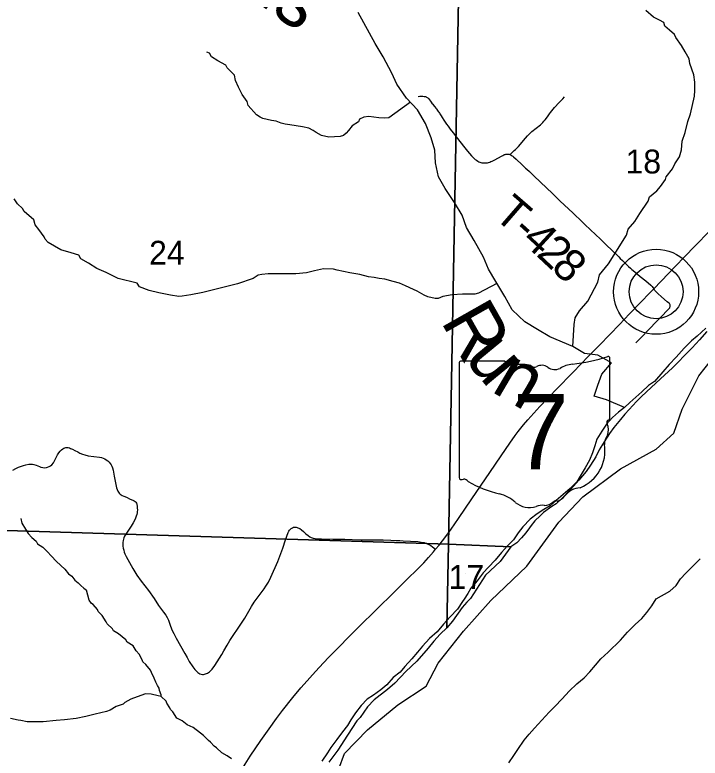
# Model space of a CAD drawing. Extents: x 6.3 to 40.3, y 9 to 31.
# Drawn here: x 9.509 to 10.708, y 23.853 to 25.154 of the extents above; entities that cross this region are included whole.
import ezdxf

# ---------------------------------------------------------------- set-up
doc = ezdxf.new("R2010")
doc.units = 0
for name, color, linetype in [('Default', 7, 'Continuous'), ('GM_X_Major_River', 7, 'Continuous'), ('GM_X_Minor_River', 7, 'Continuous'), ('GM_X_Minor_River_Text', 7, 'Continuous'), ('GM_X_Section', 7, 'Continuous'), ('GM_X_Section_Text', 7, 'Continuous'), ('GM_X_State_Location', 7, 'Continuous'), ('GM_X_State_Route', 7, 'Continuous'), ('GM_X_State_Shield', 7, 'Continuous'), ('GM_X_Township_Road', 7, 'Continuous'), ('GM_X_Township_Road_Text', 7, 'Continuous'), ('GM_X_Unincorporated', 7, 'Continuous'), ('GM_X_Unincorporated_Location', 7, 'Continuous'), ('SH_Cut_Line', 7, 'Continuous')]:
    doc.layers.add(name, color=color, linetype=linetype)

msp = doc.modelspace()

# ---------------------------------------------------------------- linework, layer by layer
at = {"layer": 'Default'}
msp.add_lwpolyline([(10.0659, 23.8074), (10.0861, 23.8612), (10.1261, 23.9024), (10.1794, 23.946), (10.2287, 23.9786), (10.2497, 24.0192), (10.2941, 24.0752), (10.3423, 24.1287), (10.4051, 24.1886), (10.4609, 24.2658), (10.5028, 24.3104), (10.5689, 24.3593), (10.6314, 24.3933), (10.6625, 24.4218), (10.6767, 24.4634), (10.7062, 24.5216), (10.7617, 24.5919)], dxfattribs=at)
at = {"layer": 'GM_X_Major_River'}
for points in [[(10.7184, 24.6053), (10.7031, 24.5914), (10.693, 24.5832), (10.6804, 24.5705), (10.6662, 24.5547), (10.6539, 24.5419), (10.6428, 24.5288), (10.6283, 24.5119), (10.6182, 24.5049), (10.6063, 24.494), (10.5854, 24.4754), (10.5757, 24.4665), (10.5656, 24.4584), (10.5551, 24.4491), (10.5447, 24.4372), (10.5362, 24.4249), (10.5273, 24.411), (10.5238, 24.3992), (10.5198, 24.387), (10.5147, 24.374), (10.507, 24.361), (10.4982, 24.3464), (10.4923, 24.3364), (10.4807, 24.3249), (10.4684, 24.314), (10.4564, 24.3036), (10.446, 24.2946), (10.4347, 24.288), (10.4231, 24.2806), (10.4108, 24.2712), (10.3981, 24.2574), (10.3899, 24.2473), (10.3818, 24.2351), (10.3714, 24.2242), (10.3606, 24.2127), (10.3495, 24.1992), (10.3379, 24.1868), (10.3286, 24.1772), (10.3179, 24.163), (10.3071, 24.1502), (10.3016, 24.1407), (10.2953, 24.1311), (10.2923, 24.1267)], [(10.6553, 24.1449), (10.6665, 24.155), (10.6742, 24.1665), (10.6835, 24.1765), (10.6951, 24.1881), (10.7085, 24.2016)], [(10.3734, 23.8446), (10.3823, 23.8576), (10.389, 23.868), (10.4004, 23.8845), (10.409, 23.8945), (10.4187, 23.9052), (10.4313, 23.9191), (10.4443, 23.9334), (10.454, 23.943), (10.4667, 23.9565), (10.479, 23.97), (10.4928, 23.9831), (10.5055, 23.9936), (10.5151, 24.0036), (10.5252, 24.0155), (10.5348, 24.0267), (10.5475, 24.0383), (10.5692, 24.0591), (10.581, 24.0733), (10.5948, 24.0865), (10.6064, 24.0969), (10.6153, 24.1077), (10.6238, 24.1192), (10.6315, 24.1314), (10.6553, 24.1449)], [(10.2923, 24.1267), (10.2838, 24.1133), (10.2711, 24.1002), (10.2592, 24.0871), (10.2481, 24.0736), (10.2346, 24.062), (10.2227, 24.0489), (10.2138, 24.0385), (10.2038, 24.0266), (10.1915, 24.0131), (10.1833, 24.0031), (10.1714, 23.9938), (10.1598, 23.9811), (10.1494, 23.9722), (10.137, 23.9629), (10.1258, 23.9559), (10.115, 23.9447), (10.1053, 23.932), (10.0972, 23.9198), (10.0913, 23.9098), (10.0824, 23.8987), (10.0724, 23.8852), (10.062, 23.8714), (10.0561, 23.8618), (10.0461, 23.8476)]]:
    msp.add_lwpolyline(points, dxfattribs=at)
at = {"layer": 'GM_X_Minor_River'}
for points in [[(10.5757, 24.4665), (10.5445, 24.4797), (10.5229, 24.4861), (10.5293, 24.5054), (10.5365, 24.5246), (10.5532, 24.5446), (10.5293, 24.5578), (10.5062, 24.5608), (10.4854, 24.5733), (10.4453, 24.5899), (10.4237, 24.6027), (10.4014, 24.6163), (10.3794, 24.6374), (10.3665, 24.6608), (10.3506, 24.6869), (10.3381, 24.7084), (10.3294, 24.7295), (10.3128, 24.759), (10.2995, 24.7812), (10.2916, 24.8031), (10.2787, 24.8254), (10.262, 24.8499), (10.2507, 24.8699), (10.245, 24.8944), (10.2442, 24.9167), (10.2374, 24.9386), (10.228, 24.9635), (10.2139, 24.9873), (10.1946, 25.008), (10.1776, 25.0322), (10.1689, 25.0518), (10.1537, 25.0801), (10.1397, 25.1035), (10.1098, 25.1575)], [(10.4854, 24.5733), (10.488, 24.6115), (10.4894, 24.6233), (10.4973, 24.6359), (10.5119, 24.6524), (10.5294, 24.6856), (10.5323, 24.6985), (10.548, 24.7177), (10.5607, 24.7383), (10.5794, 24.7681), (10.5823, 24.7784), (10.5939, 24.7918), (10.6029, 24.806), (10.6175, 24.8278), (10.6197, 24.835), (10.6325, 24.8454), (10.6392, 24.8534), (10.6478, 24.8653), (10.6489, 24.8703), (10.6602, 24.8844), (10.6642, 24.8928), (10.6721, 24.9054), (10.6754, 24.9172), (10.6771, 24.9324), (10.6823, 24.9477), (10.6866, 24.9667), (10.6914, 24.9804), (10.6987, 25.0116), (10.6993, 25.0215), (10.6988, 25.0356), (10.6971, 25.0485), (10.6905, 25.0685), (10.6892, 25.0769), (10.6823, 25.0889), (10.6757, 25.1002), (10.6657, 25.1142), (10.6637, 25.1195), (10.6545, 25.127), (10.6465, 25.1341), (10.6445, 25.1402), (10.6369, 25.1446), (10.6265, 25.1498), (10.6131, 25.1615)], [(10.2015, 25.0007), (10.1633, 24.9736), (10.1557, 24.9728), (10.1458, 24.9734), (10.1371, 24.9745), (10.1283, 24.9759), (10.12, 24.9743), (10.1124, 24.9708), (10.1106, 24.9666), (10.0996, 24.9593), (10.0929, 24.9512), (10.0891, 24.9466), (10.0842, 24.9424), (10.0786, 24.9408), (10.0588, 24.9395), (10.0455, 24.9424), (10.0363, 24.9476), (10.031, 24.9513), (10.0237, 24.9554), (10.0123, 24.9576), (9.9902, 24.9612), (9.9819, 24.9626), (9.975, 24.964), (9.9663, 24.9673), (9.9583, 24.9688), (9.943, 24.972), (9.9385, 24.9743), (9.932, 24.9788), (9.9174, 24.9949), (9.9154, 25.0021), (9.9069, 25.0142), (9.9007, 25.027), (9.8952, 25.0387), (9.8936, 25.0482), (9.8809, 25.061), (9.8786, 25.0655), (9.8645, 25.0729), (9.853, 25.0804), (9.8499, 25.0868), (9.8453, 25.0884)], [(10.3527, 24.6835), (10.3204, 24.6666), (10.3139, 24.665), (10.2927, 24.6648), (10.2741, 24.6639), (10.2581, 24.661), (10.2498, 24.6575), (10.2445, 24.6575), (10.232, 24.6604), (10.2255, 24.6633), (10.2132, 24.67), (10.2068, 24.673), (10.193, 24.6793), (10.1823, 24.6838), (10.1709, 24.6871), (10.1568, 24.6911), (10.1465, 24.6925), (10.1378, 24.6939), (10.1279, 24.6953), (10.1127, 24.699), (10.0952, 24.7022), (10.0731, 24.7069), (10.0666, 24.7087), (10.0495, 24.7093), (10.0336, 24.7057), (10.0196, 24.7021), (10.001, 24.7004), (9.9638, 24.7004), (9.9524, 24.7003), (9.9414, 24.6994), (9.935, 24.6982), (9.9263, 24.6924), (9.8987, 24.6826), (9.8381, 24.6675), (9.8173, 24.6635), (9.8021, 24.6611), (9.796, 24.6606), (9.7816, 24.6628), (9.761, 24.6671), (9.7443, 24.6715), (9.7271, 24.6774), (9.7229, 24.6841), (9.6901, 24.6922), (9.6687, 24.7026), (9.6527, 24.7096), (9.6382, 24.7189), (9.6248, 24.7268), (9.6209, 24.7328), (9.6076, 24.7372), (9.5893, 24.7423), (9.5675, 24.755), (9.5622, 24.761), (9.5606, 24.7652), (9.5556, 24.7716), (9.551, 24.778), (9.5444, 24.7859), (9.5421, 24.7946), (9.5252, 24.8096), (9.5228, 24.8149), (9.5136, 24.8228), (9.5079, 24.8314)], [(9.5198, 24.2723), (9.5214, 24.2639), (9.5275, 24.2537), (9.5322, 24.2458), (9.5387, 24.2387), (9.5464, 24.2323), (9.5487, 24.2281), (9.5583, 24.2218), (9.5656, 24.2143), (9.5732, 24.206), (9.5817, 24.1977), (9.5894, 24.1899), (9.5963, 24.1835), (9.6028, 24.1752), (9.6086, 24.1711), (9.6139, 24.1643), (9.6197, 24.1598), (9.6247, 24.1549), (9.6301, 24.15), (9.6343, 24.1467)], [(10.2973, 24.1765), (10.2973, 24.1765)], [(9.7651, 23.9604), (9.7653, 23.9634), (9.7623, 23.9709), (9.7618, 23.9751), (9.7585, 23.9799), (9.756, 23.9855), (9.753, 23.9926), (9.748, 24.0027), (9.7463, 24.0065), (9.7386, 24.0168), (9.7331, 24.0216), (9.7318, 24.0246), (9.7264, 24.0346), (9.7216, 24.0405), (9.7159, 24.0495), (9.7057, 24.0556), (9.7033, 24.0596), (9.6906, 24.0706), (9.6817, 24.0756), (9.68, 24.0789), (9.6705, 24.0877), (9.6692, 24.0915), (9.6619, 24.1026), (9.6548, 24.1092), (9.6535, 24.113), (9.6462, 24.1218), (9.6431, 24.1236), (9.6391, 24.1295), (9.6343, 24.1467)], [(9.8883, 23.8516), (9.8809, 23.8566), (9.8715, 23.862), (9.8617, 23.8707), (9.8581, 23.8737), (9.8517, 23.881), (9.8482, 23.8839), (9.8394, 23.8924), (9.834, 23.8963), (9.821, 23.9065), (9.8106, 23.9111), (9.8019, 23.918), (9.7926, 23.9226), (9.7853, 23.9337), (9.7813, 23.9378), (9.7804, 23.9408), (9.7751, 23.9493), (9.7738, 23.9527), (9.7651, 23.9604), (9.7597, 23.9621), (9.7475, 23.965), (9.738, 23.9651), (9.7298, 23.9625), (9.7119, 23.9561), (9.7016, 23.9504), (9.6987, 23.9472), (9.6864, 23.943), (9.6761, 23.9369), (9.6694, 23.9347), (9.6495, 23.9298), (9.6335, 23.9254), (9.6166, 23.9221), (9.5959, 23.9198), (9.5812, 23.9185), (9.5589, 23.9165), (9.5438, 23.9163), (9.5309, 23.9162), (9.5194, 23.9185), (9.5149, 23.9194), (9.5015, 23.9223)]]:
    msp.add_lwpolyline(points, dxfattribs=at)
at = {"layer": 'GM_X_Section'}
for points in [[(9.286, 25.2685), (10.2864, 25.2447), (10.2678, 24.2273), (9.2683, 24.2583)], [(10.2678, 24.2273), (10.377, 24.2225), (10.3585, 24.1969), (10.3329, 24.173), (10.3064, 24.1322), (10.3, 24.1256), (10.2919, 24.1164), (10.2752, 24.0926), (10.2651, 24.0807)]]:
    msp.add_lwpolyline(points, close=True, dxfattribs=at)
for points in [[(10.72, 24.5997), (10.7069, 24.5848), (10.6943, 24.5709), (10.6812, 24.5574), (10.6697, 24.5455), (10.66, 24.5359), (10.6391, 24.5166), (10.6226, 24.5012), (10.6058, 24.4858), (10.5972, 24.4769), (10.5842, 24.4627), (10.5764, 24.455), (10.569, 24.4454), (10.557, 24.4312), (10.5496, 24.4208), (10.5404, 24.4066), (10.5315, 24.3921), (10.5257, 24.3799), (10.5164, 24.3657), (10.509, 24.3542), (10.496, 24.3392), (10.4822, 24.3235), (10.4669, 24.3077), (10.4565, 24.2981), (10.4486, 24.293), (10.4343, 24.2829), (10.4284, 24.2771), (10.4191, 24.2679), (10.4124, 24.2602), (10.4098, 24.256), (10.4035, 24.2472), (10.3956, 24.2384), (10.3874, 24.2299), (10.377, 24.2225), (10.2678, 24.2273), (10.2864, 25.2447)], [(9.2503, 23.246), (9.2683, 24.2583), (10.2678, 24.2273), (10.2651, 24.0807), (10.2532, 24.0699), (10.2424, 24.0573), (10.2324, 24.045), (10.2126, 24.0223), (10.1932, 24.0046), (10.1738, 23.9838), (10.1615, 23.973), (10.1379, 23.9548), (10.1264, 23.9425), (10.1134, 23.9241), (10.1074, 23.9183), (10.0915, 23.893), (10.0745, 23.867), (10.0585, 23.8459)]]:
    msp.add_lwpolyline(points, dxfattribs=at)
at = {"layer": 'GM_X_State_Route'}
for points in [[(10.5848, 24.6304), (10.604, 24.6503), (10.6208, 24.6678), (10.6271, 24.6744), (10.6527, 24.7008), (10.6799, 24.729), (10.7007, 24.7504), (10.7038, 24.7535), (10.7543, 24.8058), (10.8131, 24.8664), (10.8327, 24.8872), (10.8454, 24.9), (10.8683, 24.9237), (10.8938, 24.95), (10.9069, 24.9641), (10.9227, 24.9816), (10.9375, 24.9992), (10.9472, 25.0107)], [(10.509, 24.552), (10.5319, 24.5757), (10.55, 24.5945), (10.5669, 24.6118), (10.5848, 24.6304)], [(10.0207, 23.9882), (10.0298, 23.9985), (10.0416, 24.0114), (10.0582, 24.029), (10.0778, 24.0489), (10.0918, 24.0631), (10.1111, 24.0825), (10.1727, 24.143), (10.1895, 24.1596), (10.1973, 24.1676), (10.2119, 24.182), (10.2246, 24.1948), (10.233, 24.2039), (10.242, 24.2141), (10.2454, 24.2184), (10.2514, 24.2256), (10.2632, 24.2408), (10.2728, 24.2538), (10.2856, 24.2721), (10.3089, 24.3066), (10.3403, 24.3529), (10.3604, 24.3821), (10.3753, 24.4042), (10.3847, 24.4174), (10.3899, 24.4244), (10.3993, 24.4361), (10.4066, 24.4446), (10.4279, 24.468), (10.4411, 24.482), (10.4606, 24.5021), (10.5034, 24.5462), (10.509, 24.552)], [(9.7553, 23.5432), (9.7643, 23.5614), (9.7815, 23.5958), (9.8021, 23.6369), (9.8337, 23.7003), (9.8605, 23.7536), (9.8693, 23.7701), (9.8821, 23.7928), (9.8967, 23.8174), (9.912, 23.8424), (9.9211, 23.8564), (9.9397, 23.8836), (9.9539, 23.9041), (9.9671, 23.9222), (9.9777, 23.936), (9.9958, 23.9589), (10.0097, 23.9756), (10.0207, 23.9882)]]:
    msp.add_lwpolyline(points, dxfattribs=at)
at = {"layer": 'GM_X_State_Shield'}
for p, q in [((10.3663, 24.5476), (10.2891, 24.5476)), ((10.5502, 24.4479), (10.5502, 24.5526)), ((10.2865, 24.5442), (10.2865, 24.3441)), ((10.5502, 24.4479), (10.5502, 24.4479))]:
    msp.add_line(p, q, dxfattribs=at)
for centre, radius, start, end in [((10.2895, 24.5446), 0.00305, 98.1301, 188.1301), ((10.3847, 24.5709), 0.0296, 231.6195, 271.1119), ((10.4563, 24.8205), 0.2796, 275.8445, 288.9065), ((10.5473, 24.553), 0.00294, 351.8621, 97.738), ((10.3946, 24.4353), 0.1064, 80.4867, 94.9883), ((10.4187, 24.5457), 0.00855, 219.7921, 297.1024), ((10.4312, 24.5225), 0.0178, 54.4667, 119.1411), ((10.4542, 24.5543), 0.0214, 233.8562, 294.8282), ((10.4919, 24.4865), 0.0563, 97.3462, 120.7689), ((10.5495, 24.4402), 0.00454, 107.944, 210.337), ((10.5471, 24.4475), 0.00314, 289.6038, 7.7341), ((10.5206, 24.427), 0.0273, 340.033, 23.6496), ((10.5607, 24.4041), 0.0198, 136.8065, 186.9296), ((10.4719, 24.3908), 0.0699, 292.3089, 8.9858), ((10.2896, 24.3436), 0.00308, 171.9584, 258.3066), ((10.29, 24.3641), 0.0235, 267.339, 280.6039), ((10.2949, 24.3325), 0.00848, 29.7484, 93.2717), ((10.4019, 24.5123), 0.2019, 240.4129, 257.1985), ((10.5014, 24.2879), 0.0383, 94.4031, 142.5768), ((10.3417, 24.2542), 0.0632, 47.1842, 75.836), ((10.41, 24.3315), 0.0401, 230.7004, 286.2918), ((10.4361, 24.3166), 0.0214, 268.777, 315.5493), ((10.4555, 24.2972), 0.00601, 65.7517, 132.6484), ((10.4529, 24.3247), 0.0226, 282.8732, 323.2771), ((10.4332, 24.2624), 0.0329, 85.6951, 111.2099)]:
    msp.add_arc(centre, radius, start, end, dxfattribs=at)
at = {"layer": 'GM_X_Township_Road'}
for points in [[(10.2149, 25.0108), (10.2179, 25.0113), (10.2191, 25.0113), (10.2204, 25.0113), (10.2229, 25.0111), (10.2253, 25.0109), (10.2276, 25.0105), (10.2286, 25.0102), (10.2295, 25.0098), (10.2307, 25.0092), (10.2316, 25.0085), (10.2322, 25.008), (10.2327, 25.0073), (10.2362, 25.0024), (10.2374, 25.0009), (10.2395, 24.998), (10.2403, 24.9971), (10.2419, 24.9953), (10.243, 24.9939), (10.2467, 24.9891), (10.2474, 24.9881), (10.2499, 24.9846), (10.2509, 24.9831), (10.252, 24.9815), (10.2526, 24.9805), (10.254, 24.9784), (10.255, 24.9768), (10.2566, 24.9741), (10.2597, 24.9694), (10.2611, 24.9674), (10.2635, 24.9638), (10.2646, 24.9623), (10.2672, 24.9587), (10.2709, 24.9538), (10.2763, 24.9469), (10.2801, 24.942), (10.2839, 24.9371), (10.294, 24.9237), (10.3011, 24.915), (10.3081, 24.9071), (10.313, 24.9022), (10.3149, 24.9007), (10.3168, 24.8991), (10.3194, 24.8974), (10.321, 24.8965), (10.3227, 24.8958), (10.3245, 24.8952), (10.3263, 24.8947), (10.3277, 24.8945), (10.3294, 24.8944), (10.3325, 24.8945), (10.3344, 24.8947), (10.3362, 24.8949), (10.3381, 24.8954), (10.3404, 24.8961), (10.3423, 24.8968), (10.3444, 24.8976), (10.3489, 24.8998), (10.3608, 24.9066), (10.3629, 24.9077), (10.3647, 24.9085), (10.3658, 24.909), (10.3671, 24.9093), (10.3682, 24.9096), (10.3694, 24.9097), (10.3705, 24.9098), (10.3718, 24.9098), (10.3731, 24.9097), (10.3744, 24.9096), (10.3751, 24.9094), (10.3758, 24.9091)], [(10.3758, 24.9091), (10.383, 24.916), (10.3852, 24.9181), (10.3883, 24.9211), (10.3904, 24.9234), (10.394, 24.9276), (10.3992, 24.9339), (10.4062, 24.9418), (10.4109, 24.9468), (10.4122, 24.948), (10.4137, 24.9492), (10.4287, 24.9614), (10.431, 24.9634), (10.4328, 24.9652), (10.4349, 24.9674), (10.4369, 24.9698), (10.441, 24.9752), (10.4446, 24.9802), (10.4465, 24.9827), (10.4489, 24.9856), (10.4537, 24.9913), (10.4617, 25), (10.4679, 25.0069), (10.4707, 25.0103)], [(10.3758, 24.9091), (10.3779, 24.9079), (10.3792, 24.9071), (10.3804, 24.9063), (10.3817, 24.9053), (10.3862, 24.9012), (10.397, 24.891), (10.4028, 24.8855), (10.4051, 24.8835), (10.4096, 24.8792), (10.4177, 24.8714), (10.4394, 24.851), (10.4497, 24.8411), (10.4636, 24.8278), (10.4779, 24.814), (10.486, 24.8063), (10.5019, 24.7915), (10.5068, 24.7867), (10.5167, 24.7774), (10.5338, 24.7612), (10.5441, 24.7513), (10.5544, 24.7415), (10.5637, 24.7323), (10.5659, 24.7301), (10.5686, 24.7275), (10.5725, 24.7235), (10.5759, 24.72), (10.5786, 24.7174), (10.583, 24.7132), (10.5862, 24.7103), (10.589, 24.7078), (10.5938, 24.7039), (10.6033, 24.6959), (10.6131, 24.6882), (10.6222, 24.6805), (10.6232, 24.6795), (10.6242, 24.6783), (10.6257, 24.6764), (10.6271, 24.6744)], [(10.5957, 24.5797), (10.604, 24.588), (10.6192, 24.6036), (10.6322, 24.6169), (10.6399, 24.625), (10.652, 24.6375), (10.6545, 24.6403), (10.655, 24.6411), (10.6555, 24.6419), (10.6559, 24.643), (10.656, 24.6436), (10.656, 24.6449), (10.6557, 24.6461), (10.6552, 24.6471), (10.6544, 24.6482), (10.6531, 24.6495), (10.6508, 24.6515), (10.6408, 24.6599), (10.6343, 24.6657), (10.6308, 24.6693), (10.6299, 24.6703), (10.6291, 24.6713), (10.6282, 24.6726), (10.6271, 24.6744)], [(9.5056, 24.3568), (9.5109, 24.3598), (9.5153, 24.3618), (9.5188, 24.3632), (9.5241, 24.3648), (9.5286, 24.366), (9.5335, 24.367), (9.5372, 24.3673), (9.5403, 24.3671), (9.5421, 24.3668), (9.5463, 24.3654), (9.552, 24.363), (9.5543, 24.3621), (9.5579, 24.3612), (9.5616, 24.361), (9.5647, 24.3614), (9.5665, 24.3618), (9.5693, 24.3631), (9.5714, 24.3644), (9.5738, 24.3664), (9.5766, 24.3697), (9.5791, 24.374), (9.5838, 24.3834), (9.586, 24.3872), (9.5883, 24.3901), (9.5905, 24.3923), (9.593, 24.3942), (9.5946, 24.3951), (9.5965, 24.3958), (9.5983, 24.3962), (9.6004, 24.3964), (9.6024, 24.3963), (9.6045, 24.3957), (9.6066, 24.3949), (9.6101, 24.3933), (9.6143, 24.3911), (9.6191, 24.3886), (9.6231, 24.3866), (9.6277, 24.3846), (9.6314, 24.3834), (9.6375, 24.3821), (9.657, 24.3795), (9.6605, 24.3788), (9.6635, 24.3779), (9.6665, 24.3765), (9.6692, 24.3749), (9.6719, 24.373), (9.6742, 24.3709), (9.6761, 24.3686), (9.6778, 24.366), (9.679, 24.3639), (9.68, 24.3609), (9.681, 24.3567), (9.6828, 24.3463), (9.6872, 24.3261), (9.6882, 24.3228), (9.6893, 24.32), (9.6905, 24.318), (9.6918, 24.3165), (9.6934, 24.315), (9.6954, 24.3136), (9.6971, 24.3127), (9.6997, 24.3115), (9.7044, 24.3093), (9.7112, 24.3062), (9.7155, 24.3043), (9.7181, 24.303), (9.7198, 24.3018), (9.7211, 24.3006), (9.7221, 24.299), (9.7227, 24.297), (9.723, 24.2933), (9.7234, 24.2902), (9.7235, 24.2871), (9.7234, 24.2841), (9.7232, 24.2821), (9.7226, 24.2792), (9.7216, 24.2763), (9.7196, 24.2711), (9.7163, 24.2646), (9.7125, 24.2588), (9.7056, 24.2485), (9.7031, 24.2449), (9.701, 24.2411), (9.7, 24.2382), (9.6988, 24.2338), (9.6982, 24.2301), (9.698, 24.227), (9.6982, 24.2238), (9.6988, 24.2202), (9.6996, 24.2166), (9.7006, 24.2134), (9.7018, 24.2102), (9.7039, 24.2057), (9.7157, 24.1847), (9.7223, 24.1728), (9.7301, 24.1625), (9.7429, 24.1462), (9.7528, 24.132), (9.7606, 24.1198), (9.7693, 24.1081), (9.7731, 24.103), (9.7755, 24.099), (9.7778, 24.094), (9.7801, 24.0874), (9.7839, 24.0774), (9.7874, 24.0707), (9.7914, 24.063), (9.799, 24.0493), (9.8064, 24.0361), (9.8105, 24.0287), (9.8144, 24.0221), (9.8207, 24.0125), (9.824, 24.0079), (9.8269, 24.0049), (9.8291, 24.0029), (9.831, 24.0014), (9.8329, 24.0005), (9.835, 23.9998), (9.8373, 23.9994), (9.8392, 23.9993), (9.841, 23.9995), (9.8429, 24.0001), (9.8447, 24.0007), (9.8465, 24.0018), (9.8497, 24.0041), (9.8518, 24.006), (9.8542, 24.0085), (9.8591, 24.0151), (9.8711, 24.0344), (9.8748, 24.0405), (9.8805, 24.0507), (9.8827, 24.0545), (9.8853, 24.0587), (9.891, 24.0675), (9.8998, 24.0802), (9.9047, 24.0874), (9.908, 24.0926), (9.9113, 24.0979), (9.916, 24.1059), (9.9233, 24.1182), (9.9279, 24.1256), (9.9454, 24.1492), (9.9485, 24.1538), (9.9527, 24.1608), (9.957, 24.1697), (9.9692, 24.1967), (9.9783, 24.2201), (9.9827, 24.2349), (9.9875, 24.2478), (9.9886, 24.2501), (9.9897, 24.2518), (9.9912, 24.2535), (9.9924, 24.2547), (9.9948, 24.2561), (9.9968, 24.2568), (9.999, 24.257), (10.0012, 24.2569), (10.003, 24.2565), (10.0044, 24.2561), (10.0062, 24.2555), (10.0079, 24.2546), (10.0107, 24.2524), (10.0141, 24.2495), (10.0185, 24.2455), (10.0223, 24.2422), (10.0252, 24.2404), (10.0279, 24.2389), (10.0311, 24.2378), (10.0344, 24.2373), (10.0393, 24.2369), (10.0456, 24.2365), (10.0653, 24.2363), (10.079, 24.236), (10.0864, 24.2358), (10.0995, 24.2355), (10.115, 24.2351), (10.1361, 24.2349), (10.1535, 24.2348), (10.1671, 24.2344), (10.1758, 24.2339), (10.1826, 24.2335), (10.1887, 24.233), (10.2141, 24.2317), (10.2203, 24.231), (10.2252, 24.23), (10.2293, 24.2286), (10.2333, 24.2269), (10.237, 24.2248), (10.24, 24.2225), (10.2454, 24.2184)]]:
    msp.add_lwpolyline(points, dxfattribs=at)
at = {"layer": 'GM_X_Unincorporated'}
for radius in [0.0744, 0.0472]:
    msp.add_circle((10.6313, 24.669), radius, dxfattribs=at)
at = {"layer": 'GM_X_Unincorporated_Location'}
msp.add_line((10.6313, 24.669), (10.6313, 24.669), dxfattribs=at)
at = {"layer": 'SH_Cut_Line'}
msp.add_lwpolyline([(10.0659, 23.8074), (10.0861, 23.8612), (10.1261, 23.9024), (10.1794, 23.946), (10.2287, 23.9786), (10.2497, 24.0192), (10.2941, 24.0752), (10.3423, 24.1287), (10.4051, 24.1886), (10.4609, 24.2658), (10.5028, 24.3104), (10.5689, 24.3593), (10.6314, 24.3933), (10.6625, 24.4218), (10.6767, 24.4634), (10.7062, 24.5216), (10.7617, 24.5919)], dxfattribs=at)

# ---------------------------------------------------------------- texts
at = {"layer": 'GM_X_Minor_River_Text'}
for s, height, rotation, p in [('Collins', 0.09469, 324.6183, (9.6975, 25.3419)), ('R', 0.0947, 299.5272, (10.2534, 24.6178)), ('u', 0.0947, 309.5274, (10.2943, 24.552)), ('n', 0.0947, 329.5264, (10.3405, 24.4957))]:
    msp.add_text(s, height=height, rotation=rotation, dxfattribs=at).set_placement(p)
at = {"layer": 'GM_X_Section_Text'}
for s, p in [('18', (10.5777, 24.876)), ('24', (9.744, 24.7163)), ('17', (10.2681, 24.149))]:
    msp.add_text(s, height=0.04186, rotation=0, dxfattribs=at).set_placement(p)
at = {"layer": 'GM_X_State_Location'}
for s in ['s', 'r']:
    msp.add_text(s, height=0.000189, dxfattribs=at).set_placement((10.4154, 24.4308))
msp.add_text('7', height=0.000189, rotation=0, dxfattribs=at).set_placement((10.3869, 24.4171))
at = {"layer": 'GM_X_State_Shield'}
msp.add_text('7', height=0.1318, dxfattribs=at).set_placement((10.3806, 24.3582))
at = {"layer": 'GM_X_Township_Road_Text'}
for s, rotation, p in [('T', 319.0366, (10.3452, 24.8002)), ('-', 317.7331, (10.3771, 24.7726)), ('4', 317.3189, (10.3942, 24.7569)), ('2', 316.9487, (10.4199, 24.7333)), ('8', 316.8585, (10.4455, 24.7094))]:
    msp.add_text(s, height=0.0568, rotation=rotation, dxfattribs=at).set_placement(p)

doc.saveas('drawing.dxf')
